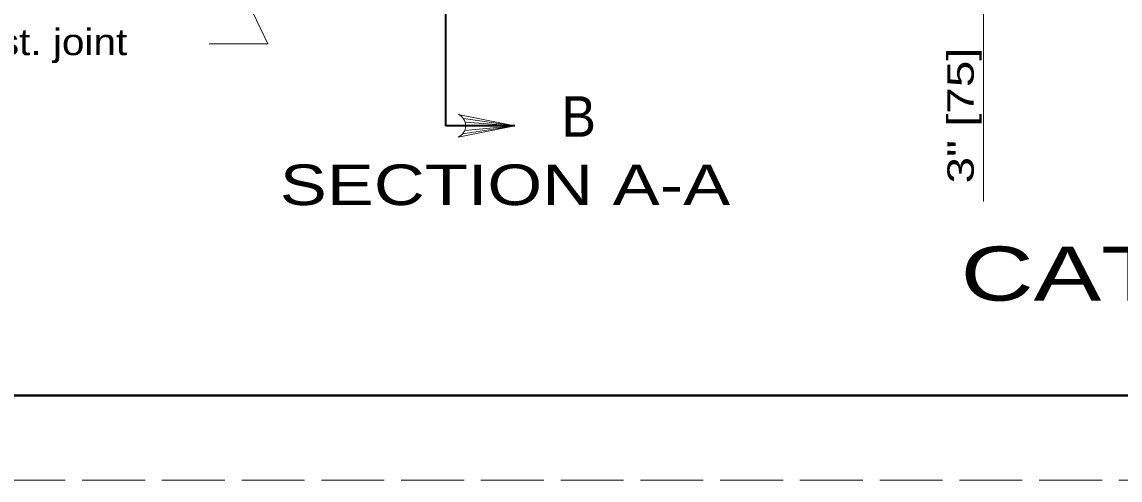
# Model space of a CAD drawing. Extents: x 1083.1 to 1117.1, y 697.4 to 719.4.
# Drawn here: x 1086.55 to 1093.04, y 697.35 to 700.07 of the extents above; entities that cross this region are included whole.
import ezdxf
from ezdxf.enums import TextEntityAlignment as Align

# ---------------------------------------------------------------- set-up
doc = ezdxf.new("R2010")
doc.units = 0
doc.header["$LTSCALE"] = 0.062
doc.linetypes.add('LONG_DASHED', pattern=[7.5, 6, -1.5])
doc.layers.add('1', color=7, linetype='Continuous', lineweight=13)

msp = doc.modelspace()

# ---------------------------------------------------------------- linework, layer by layer
at = {"layer": '1'}
for p, q in [((1092.23658, 699.00258), (1092.23658, 700.32125)), ((1089.15517, 699.40408), (1089.46333, 699.45117)), ((1089.15875, 699.49375), (1089.46333, 699.45117)), ((1089.16683, 699.42383), (1089.46333, 699.45117)), ((1089.16908, 699.47267), (1089.46333, 699.45117)), ((1089.17225, 699.45117), (1089.46333, 699.45117))]:
    msp.add_line(p, q, dxfattribs=at)
at = {"layer": '1', "lineweight": 35}
msp.add_line((1089.46333, 699.45117), (1089.05217, 699.45117), dxfattribs=at)
at = {"layer": '1', "linetype": 'LONG_DASHED'}
msp.add_lwpolyline([(1083.12642, 697.35408), (1117.12642, 697.35408), (1117.12642, 719.35408), (1083.12642, 719.35408)], close=True, dxfattribs=at)
at = {"layer": '1', "lineweight": 25}
msp.add_lwpolyline([(1116.62642, 697.85408), (1085.12642, 697.85408), (1085.12642, 718.85408)], dxfattribs=at)
at = {"layer": '1', "lineweight": 40}
msp.add_lwpolyline([(1085.12642, 718.85408), (1116.62642, 718.85408), (1116.62642, 697.85408), (1085.12642, 697.85408)], close=True, dxfattribs=at)
msp.add_lwpolyline([(1085.12642, 718.85408), (1116.62642, 718.85408), (1116.62642, 697.85408), (1085.12642, 697.85408)], close=True, dxfattribs=at)
at = {"layer": '1', "lineweight": 35}
msp.add_lwpolyline([(1089.05217, 702.26792), (1089.05217, 699.87742), (1089.05217, 699.45117)], dxfattribs=at)
at = {"layer": '1'}
for points in [[(1087.3475, 701.30158), (1088.001, 699.937), (1087.65383, 699.937)], [(1089.12692, 699.38392), (1089.46333, 699.45117), (1089.12692, 699.5185)]]:
    msp.add_lwpolyline(points, dxfattribs=at)
msp.add_arc((1089.09975, 699.45125), 0.07261, 292.08605, 67.91218, dxfattribs=at)

# ---------------------------------------------------------------- texts
for s, height, width, p in [('const. joint', 0.156, 1.15, (1086.02217, 699.86925)), ('B', 0.24, 0.95, (1089.73967, 699.386)), ('SECTION A-A', 0.24, 1.3, (1088.07183, 698.98175))]:
    msp.add_text(s, height=height, dxfattribs=dict(at, width=width)).set_placement(p)
at = {"layer": '1', "width": 1.35}
msp.add_text('3" [75]', height=0.156, rotation=90, dxfattribs=at).set_placement((1092.17908, 699.11008))
at = {"layer": '1', "width": 1.4}
msp.add_text('CATCH BASINS No. 2-3 & No. 2-4', height=0.32, dxfattribs=at).set_placement((1096.72875, 698.41617), align=Align.CENTER)

doc.saveas('drawing.dxf')
